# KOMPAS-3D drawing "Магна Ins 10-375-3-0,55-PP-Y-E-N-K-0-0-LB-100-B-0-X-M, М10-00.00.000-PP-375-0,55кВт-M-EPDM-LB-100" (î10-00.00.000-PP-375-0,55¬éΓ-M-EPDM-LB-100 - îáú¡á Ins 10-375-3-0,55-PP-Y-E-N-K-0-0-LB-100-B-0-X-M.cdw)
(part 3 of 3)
- Part/product: Магна Ins 10-375-3-0,55-PP-Y-V-N-K-0-0-L-0-B-0-X-R  | designation М10-00.00.000-PP-375-0,55кВт-R-Viton
    Масса: 11.3082
  - Component [detail]: Кольцо уплотнительное плоское 10-18-25  | designation Viton  | pos. 13  | Масса: 0.000562973; Раздел спецификации: Прочие изделия
  - Component [assembly]: Корпус полипропилен 375 0,55 кВт  / с резьбовым переходником  | designation М10-00.20.000-PP-375-0,55кВт-R  | pos. 2
      Материал: Полипропилен  ГОСТ 26996-86 (density 900 kg/m3)
      Масса: 4.99986
      Раздел спецификации: Сборочные единицы
      Форматы листов документа: 3xA3
      Примечание: @100~)3xA3@101~)3xA3
      source file: ..\М10-00.20.000 - Корпус.a3d
  - Component [assembly]: Вал  | designation М10-00.15.000-0,55кВт-375  | pos. 1
      Материал: Полипропилен  ГОСТ 26996-86 (density 900 kg/m3)
      Масса: 0.519317
      Раздел спецификации: Сборочные единицы
      Форматы листов документа: 2xA3
      Примечание: @100~)2xA3
      source file: ..\М10-00.15.000 - Вал.a3d
  - Component [detail]: Крышка  | designation М10-00.00.002  | pos. 4
      Материал: Полипропилен  ГОСТ 26996-86 (density 900 kg/m3)
      Масса: 0.324102
      Раздел спецификации: Детали
      Форматы листов документа: 4xA4
      Примечание: @100~)4xA4
      source file: ..\М10-00.00.002 - Крышка.cdw, ..\М10-00.00.002 - Крышка.m3d
  - Component [detail]: Импеллер Магна10  | designation М10-00.00.001  | pos. 3  | Масса: 0.169927; Раздел спецификации: Детали; Форматы листов документа: A3; source file: ..\М10-00.00.001 - Импеллер Магна10.cdw, ..\М10-00.00.001 - Импеллер Магна10.m3d
  - Component [detail]: Защитная втулка  | designation М10-00.00.003  | pos. 5  | Масса: 0.0193569; Раздел спецификации: Детали; Форматы листов документа: A4; source file: ..\М10-00.00.003 - Защитная втулка.cdw, ..\М10-00.00.003 - Защитная втулка.m3d
  - Component [detail]: Втулка ответная  | designation М10А-00.00.003-01  | pos. 6  | Масса: 0.031838; Раздел спецификации: Детали; Форматы листов документа: A4; Примечание: Заим.; source file: ..\..\..\..\..\..\AquaProf\АкваProf 190\3Д модель\М10А-00.00.003 - Втулка ответная.m3d, ..\М10А-00.00.003-01 - Втулка ответная.cdw

Title block, sheet 1: Наименование: Магна Ins / 10-375-3-0,55-PP-Y-E-N-K / -0-0-LB-100-B-0-X-M; designation: М10-00.00.000 - PP-375-0,55кВт-M-EPDM-LB-100; Масса: 12,38; scale: 1:4; Количество листов документа: 1; organisation: АО «Астерион»; Форматы листов документа: A3; stored path: Z:\Магна\Магна Ins\Магна ins 10\М10-00.00.000\3Д\М10-00.00.000 - Магна Ins 10-C-N.cdw; Разработал: Лифлянд

Views: Вид 1, Спереди, Разрез А-А, Выносной элемент 4, Выносной элемент А, Выносной элемент
Referenced files in Z:\Магна\Магна Ins\Магна ins 10\М10-00.00.000\3Д\: М10-00.00.000 - Магна Ins 10-C-N.a3d, М10-00.15.000 - Вал.a3d
Referenced files in D:\Magna\Магна Ins\Магна ins 10\М10-00.00.000\3Д\: М10-00.00.000 - Магна Ins 10-C-N.a3d, М10-00.20.001 - Плита опорная.m3d, М10-00.00.001 - Импеллер Магна10.m3d, М10-00.00.003 - Защитная втулка.m3d, М10-00.00.005 - Закладная М10.m3d, М10-00.00.002 - Крышка.m3d, М10-00.15.001 - Вал.m3d, М10-00.30.001 - Стенка.m3d, М10-00.25.001 - Колонна.m3d, Труба 160 S=14,6 FV PPR ф. FV PLAST.m3d, М10-00.20.000 - Корпус.a3d, М10-00.20.000 - Корпус.cdw, М10-00.15.000 - Вал.a3d, М10-00.15.000 - Вал.cdw, М10-00.00.002 - Крышка.cdw, М10-00.00.001 - Импеллер Магна10.cdw, М10-00.00.003 - Защитная втулка.cdw, М10А-00.00.003-01 - Втулка ответная.cdw, Заглушка ф20 FV PPR ф. FV-Plast.m3d, М10-00.30.000 - Обечайка.a3d, М10-00.30.002 - Обечайка.m3d, М10-00.30.003 - Труба.m3d, Труба 32 PN10 S=2,9 FV PPR ф. FV PLAST.m3d, Колено 90гр 32 FV PPR ф. FV PLAST.m3d
Referenced files in D:\AquaProf\АкваProf 190\3Д модель\: М10А-00.00.003 - Втулка ответная.m3d
Referenced files in D:\Magna\Магна Ins\Магна ins 5\М5-00.00.000 - Насос Магна ins 5-C-N\3Д модель\: М5-00.20.002 - Фиксатор.m3d, М5-00.10.002 - Фланец.m3d
Referenced files in D:\1 ПКИ 3D\РТИ\Кольца уплотнительные  плоские\: Кольцо уплотнительное плоское 10-18-25 ЕPDM.m3d
Referenced files in D:\1 ПКИ 3D\Двигатели\АИР\: Электродвигатель АИР 63В2 IM 3081 0,55кВт 3000 об..m3d, Электродвигатель 3ф. АИР 71А2 380В 0,75кВт 3000об_мин 3081 DRIVE IEK.m3d
Referenced files in D:\Magna\Магна Ins\Магна ins 11\Магна N\3Д\Магна INS 11\: Всасывающая трубка 75.m3d
Referenced files in C:\Program Files\ASCON\KOMPAS-3D v18\Libs\PARTLib\DATA\vault\Methods\Kompas\3D\: PLib_Ring_9833-73_712.m3d
Referenced files in D:\1 ПКИ 3D\Двигатели\АИР\Двигатель без габарита в СП\: Электродвигатель АИР 63В2 IM 3081 0,55кВт 3000 об..m3d
Referenced files in D:\AquaProf\АкваProf 190\3Д модель\..\..\..\Magna\Магна Ins\Магна ins 10\М10-00.00.000\3Д\: М10А-00.00.003-01 - Втулка ответная.cdw
Referenced files in D:\Magna\Магна Ins\Магна ins 11\Магна N\3Д\Магна INS 11\Чертежи\: М11-00.00.004-01 - Крышка.cdw
Referenced files in D:\1 ПКИ 3D\Полипропиленовые фитинги, трубы\Разборные муфты\: Муфта разъёмная 32.m3d
Referenced files in C:\Program Files\ASCON\KOMPAS-3D v18\Libs\PartLib\DATA\VAULT\methods\kompas\3d\: PLib_Screw_GOST_8878-84_900.m3d, PLib_Screw_GOST_11074-84_900.m3d, PLib_Washer_1_712.m3d, PLib_Washer_2_712.m3d, PLib_Nut_OST92_900.m3d, PLib_Bolt_1_900.m3d
Referenced files in C:\Program Files\ASCON\KOMPAS-3D V16\Libs\PartLib\DATA\VAULT\Methods\kompas\3d\: PLib_Screw_GOST_11074-84_900.m3d
Referenced files in Z:\АкваProf\АкваProf 190\3Д модель\: М10А-00.00.003 - Втулка ответная.m3d
Referenced files in Z:\1 ПКИ 3D\Двигатели\АИР\: Электродвигатель АИР 63В2 IM 3081 0,55кВт 3000 об..m3d
Referenced files in Z:\1 ПКИ 3D\РТИ\Кольца уплотнительные  плоские\: Кольцо плоское уплотнительное 10-23-25 EPDM.m3d
Referenced files in C:\Program Files\ASCON\KOMPAS-3D V16\Libs\PartLib\DATA\vault\Methods\Kompas\3D\: PLib_Screw_GOST_8878-84_900.m3d
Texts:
  Позиции 1
  Кернить термически
  в 3 точка
  Корпус
  @100~)3xA3@101~)3xA3
  М10-00.20.000-PP
  Вал
  @100~)2xA3
  Крышка
  @100~)4xA4
  Импеллер Магна10
  Защитная втулка
  Втулка ответная
  Заим.
  Электродвигатель
  IM 3081 3000 об/мин IP55
  Электродвигатель  / IM 3081 3000 об/мин IP55
  См. заказ
  Шайба C.8.21 ГОСТ 11371-78
  Крепежное изделие ГОСТ
  Шайба
  ГОСТ
  Шайба 8 ГОСТ 6402-70
  Нерж.
  Гайка М8-6H.21.12Х18Н10Т ГОСТ 5915-70
  Гайка
  Болт М8-6gx55.21.12Х18Н10Т ГОСТ 7798-70
  Болт
  Заглушка  20 FV PPR ф. "FV-Plast"
  Заглушка @2~20 FV PPR ф. "FV-Plast"
  EPDM
  Кольцо уплотнительное плоское 10-18-25
  Шайба C.10.21 ГОСТ 11371-78
  Viton
  М10-00.20.000 - PP-375-0,55кВт-R
  М10-00.20.000 - PP-375-0,55кВт-R
  Корпус полипропилен 375 0,55 кВт
  с резьбовым переходником
  Корпус полипропилен 375 0,55 кВт  / с резьбовым переходником
  М10-00.20.000-PP-375-0,55кВт-R
  М10-00.15.000 - 0,55кВт-375
  М10-00.15.000 - 0,55кВт-375
  Электродвигатель АИР 63В2
  IM 3081 0,55кВт 3000 об/мин
  Электродвигатель АИР 63В2 / IM 3081 0,55кВт 3000 об/мин
  IP55
  Шайба 10 ГОСТ 6402-70
  Болт М8-6gx60.21.12Х18Н10Т ГОСТ 7798-70
  М10-00.15.000 - 0,75кВт-475
  М10-00.15.000 - 0,75кВт-475
  Гайка М10x1,25-6H(S16) ГОСТ 5915-70
  Электродвигатель 3ф. АИР 71А2
  380В 0,75кВт 3000 об/мин 3081 DRIVE IEK
  арт.DRV071-A2-000-8-3030
  Электродвигатель 3ф. АИР 71А2 / 380В 0,75кВт 3000 об/мин 3081 DRIVE IEK / арт.DRV071-A2-000-8-3030
  Заглушка  25 FV PPR ф. "FV-Plast"
  Заглушка @2~25 FV PPR ф. "FV-Plast"
  М10-00.20.000 - PP-475-0,75кВт-M
  М10-00.20.000 - PP-475-0,75кВт-M
  Корпус полипропилен 475 0,75кВт
  с разъёмной муфтой
  Корпус полипропилен 475 0,75кВт  / с разъёмной муфтой
  М10-00.20.000 - PP-475-0,55кВт-M
  М10-00.20.000 - PP-475-0,55кВт-M
  Корпус полипропилен 475 0,55кВт
  Корпус полипропилен 475 0,55кВт  / с разъёмной муфтой
  М10-00.15.000 - 0,55кВт-475
  М10-00.15.000 - 0,55кВт-475
  М10-00.20.000 - PP-375-0,55кВт-M
  М10-00.20.000 - PP-375-0,55кВт-M
  Корпус полипропилен 375 0,55 кВт  / с разъёмной муфтой
  М10-00.20.000-PP-375-0,55кВт-M
  Кольцо 125-130-25-1-0 ГОСТ 9833-73
  Кольцо
  Всасывающая трубка 75
  @100~)3xA3
  Кольцо 058-064-36-1-0 ГОСТ 9833-73
  М10-00.15.000-0,55кВт-375
  АИР 71B2 IM 3081 IP55 ф."Элком"
  Электродвигатель / АИР 71B2 IM 3081 IP55 ф."Элком"
  Болт М10x1,25-6gx60 (S16) ГОСТ 7798-70
  Гайка М10-6H.21.12Х18Н10Т ГОСТ 5915-70
  М10-00.20.000 - PP-375-1,1кВт-R
  М10-00.20.000 - PP-375-1,1кВт-R
  Корпус полипропилен 375 1,1кВт
  Корпус полипропилен 375 1,1кВт  / с резьбовым переходником
  М10-00.15.000 - 1,1кВт-375
  М10-00.15.000 - 1,1кВт-375
  М10-00.20.000 - PP-475
  М10-00.20.000 - PP-475
  Корпус полипропилен
  М10-00.15.000 - 0,75кВт-425
  М10-00.15.000 - 0,75кВт-425
  Болт М10-6gx60.21.12Х18Н10Т ГОСТ 7798-70
  М10-00.20.000 - PP-425-0,75кВт-R
  М10-00.20.000 - PP-425-0,75кВт-R
  Корпус полипропилен 425 0,75кВт
  Корпус полипропилен 425 0,75кВт  / с резьбовым переходником
  М10-00.20.000 - PP-475-0,75кВт
  М10-00.20.000 - PP-475-0,75кВт
  М10-00.15.000 - 1,1кВт-425
  М10-00.15.000 - 1,1кВт-425
  М10-00.20.000 - PP-425-1,1кВт-M
  М10-00.20.000 - PP-425-1,1кВт-M
  Корпус полипропилен 425 1,1кВт
  Корпус полипропилен 425 1,1кВт  / с разъёмной муфтой
  М10-00.20.000 - PP-475-0,55кВт-R
  М10-00.20.000 - PP-475-0,55кВт-R
  Корпус полипропилен 475 0,55кВт  / с резьбовым переходником
  М10-00.15.000 - 0,55кВт-425
  М10-00.15.000 - 0,55кВт-425
  М10-00.20.000 - PP-425-0,55кВт
  М10-00.20.000 - PP-425-0,55кВт
  Корпус полипропилен 425 0,55кВт
  М10-00.20.000 - PP-375-0,75кВт-M
  М10-00.20.000 - PP-375-0,75кВт-M
  Корпус полипропилен 375 0,75кВт
  Корпус полипропилен 375 0,75кВт  / с разъёмной муфтой
  М10-00.20.000-PP-375-0,75кВт-M
  М10-00.15.000 - 0,75кВт-375
  М10-00.15.000 - 0,75кВт-375
  М10-00.15.000-0,75кВт-375
  М10-00.20.000 - PP-425-0,55кВт-M
  М10-00.20.000 - PP-425-0,55кВт-M
  Корпус полипропилен 425 0,55кВт  / с разъёмной муфтой
  М10-00.20.000 - PP-375-0,55кВт
  М10-00.20.000 - PP-375-0,55кВт
  М10-00.20.000 - PP-475-1,1кВт
  М10-00.20.000 - PP-475-1,1кВт
  Корпус полипропилен 475 1,1кВт
  М10-00.15.000 - 1,1кВт-475
  М10-00.15.000 - 1,1кВт-475
  М10-00.20.000 - PP-375-1,1кВт-M
  М10-00.20.000 - PP-375-1,1кВт-M
  Корпус полипропилен 375 1,1кВт  / с разъёмной муфтой
  М10-00.15.000 - 0,75кВт
  М10-00.15.000 - 0,75кВт
  М10-00.20.000 - PP-375-0,75кВт
  М10-00.20.000 - PP-375-0,75кВт
  М10-00.20.000 - PP-375-0,75кВт-R
  М10-00.20.000 - PP-375-0,75кВт-R
  Корпус полипропилен 375 0,75кВт  / с резьбовым переходником
  М10-00.20.000 - PP-425-1,1кВт
  М10-00.20.000 - PP-425-1,1кВт
  М10-00.20.000 - PP-425-0,75кВт-M
  М10-00.20.000 - PP-425-0,75кВт-M
  Корпус полипропилен 425 0,75кВт  / с разъёмной муфтой
  М10-00.20.000 - PP-425-0,75кВт
  М10-00.20.000 - PP-425-0,75кВт
  М10-00.20.000 - PP-425-0,55кВт-R
  М10-00.20.000 - PP-425-0,55кВт-R
  Корпус полипропилен 425 0,55кВт  / с резьбовым переходником
  М10-00.20.000 - PP-425-1,1кВт-R
  М10-00.20.000 - PP-425-1,1кВт-R
  Корпус полипропилен 425 1,1кВт с резьбовым переходником
  М10-00.20.000 - PP-475-0,75кВт-R
  М10-00.20.000 - PP-475-0,75кВт-R
  Корпус полипропилен 475 0,75кВт м резьбовым переходником
  М10-00.20.000 - PP-475-1,1кВт-M
  М10-00.20.000 - PP-475-1,1кВт-M
  Корпус полипропилен 475 1,1кВт с разъёмной муфтой
  М10-00.20.000 - PP-475-1,1кВт-R
  М10-00.20.000 - PP-475-1,1кВт-R
  Корпус полипропилен 475 1,1кВт  / с резьбовым переходником
  Для 71 и 80 габарита двигателя
  крепеж поз.8...10 заменить на М10
  Заглушка  25
  Заглушка @2~25
  болты поз.7 заменить на М10х60
  Труба 160 S=14,6 / FV PPR ф. "FV PLAST"
  Обечайка
  Стенка
  Труба 32 PN10 S=2,9 FV PPR ф. "FV PLAST"
  Труба
  Фланец
  Плита опорная
  Колено 90@1~ @2~40FV PPR ф. "FV PLAST"
  Колонна
  PP-375
  Муфта разъёмная 32
  PP-375-0,55кВт-M
  Фиксатор
  Винт A.М5-6gx12.21.12Х18Н10Т ГОСТ 8878-93
  Винт A.М10-6gx40.21.12Х18Н10Т ГОСТ 11074-93
  Закладная М10
  PP-375-0,55кВт-M-EPDM-LB-100
Dimensions and other numbers on the sheet: 4 места; 17; 16; 13; 12; 20; 22; 100; 1,5; 21; 2; 1; 7; 6; 5; 14; 15; 8; 9; 4; 3; 11; 40Х; 019; 10; 58; 12Х18Н10Т; 93; 125; 130; 25; 058; 064; 36; 1:4; 10-375-3-0,55-PP-Y-E-N-K; -0-0-LB-100-B-0-X-M; 12,38; 0,55кВт-375; 01

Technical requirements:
  *Размеры для справок.
  Общие допуски ГОСТ 30893.2-mK (H14, h14,  t2/2).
